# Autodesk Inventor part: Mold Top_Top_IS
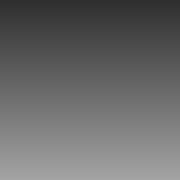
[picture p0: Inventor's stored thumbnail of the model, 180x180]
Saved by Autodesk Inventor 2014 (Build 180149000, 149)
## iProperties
Created: 2009-12
Part Number: Mold Top_Top_IS
Document SubType Name: Modeling
Designer: gaom
Density: 1 g/cm^3
Material: Generic
Appearance: Default
Author: gaom
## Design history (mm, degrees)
workplane "Work Plane2"
sketch "Sketch2"
  geometry: L1 (-2.617, 1.929)-(-2.617, 0.854) reference; L2 (-2.471, 0.66)-(-0.663, 0.146) reference; L3 (0, 0)-(0, 2.033) reference; L4 (-0.609, 2.154)-(-2.415, 2.154) reference; L5 (-0.609, 2.154)-(0, 2.154); L6 (0, 2.154)-(0, 3.654); L7 (0, 3.654)-(8.5, 3.654); L8 (8.5, 3.654)-(8.5, -1.919); L9 (6.5, -3.919)-(4.802, -3.919); L10 (4.802, -3.919)-(4.802, -3.419); L11 (-0.663, 0.146)-(0.014, -0.047); A1 r 2 centre (6.5, -1.919) between (6.5, -3.919) and (8.5, -1.919); A2 r 8.878 centre (-2.418, -8.586) between (4.802, -3.419) and (0.014, -0.047); 3 further points; 2 other entities
  constraints: 14 end point, 4 parallel, 4 point on circle, 3 tangent, 2 centre point, 2 collinear, 1 perpendicular, 2 other
  dimensions: "d8" = 0.5 distance of L9.end L10.end; "d9" = 8.5 distance of L6.end L7.end; "d10" = 1.5 distance of L5.end L6.end; "d11" = 2 radius of A1
  node "Reference11"
  node "Reference12"
  node "Reference13"
  node "Reference14"
  node "Reference15"
  node "Reference16"
  node "Reference17"
  node "Reference18"
